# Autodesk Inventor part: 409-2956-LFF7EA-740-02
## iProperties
Created: 2010-06
Part Number: 409-2956-LFF7EA-740-02
Material: Sch40 CS PIPE SEAMLESS
Description: PIPE
Document SubType Name: Modeling
Designer: S. Boerckel
Engineer: Steve Boerckel
Mass: 9098.81 g
Surface Area: 4254.05 cm^2
Volume: 1159.08 cm^3
Density: 7.85 g/cm^3
Cost Center: 3"
SMR: =<COST CENTER> - <Material>
Length: 31.740 in
Title: 4"
Author: S. Boerckel
Revision Number: B
Subject: DEMIN WATER FORWARDING PUMP SKID-7EA
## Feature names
1. Extrusion1
